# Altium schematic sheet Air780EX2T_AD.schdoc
size 124 x 121 mm
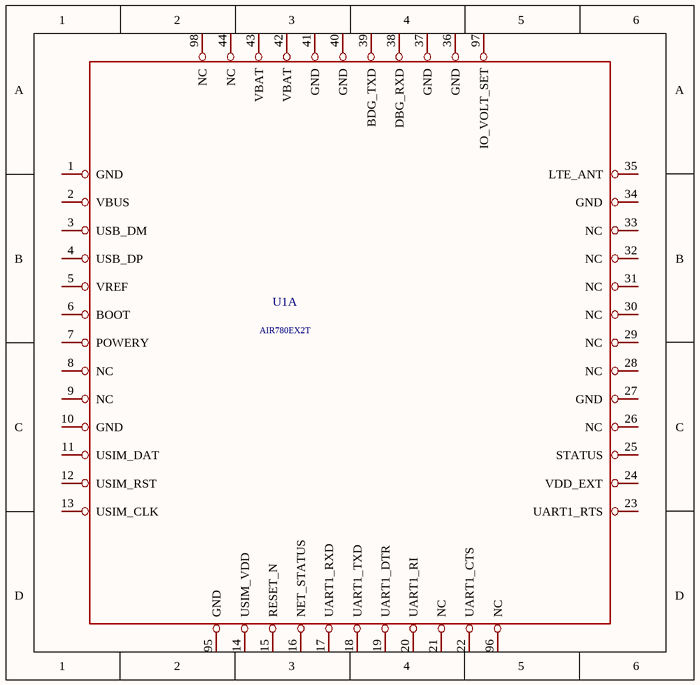
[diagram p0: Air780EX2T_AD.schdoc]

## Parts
U1  AIR780EX2T  (part A of 2)

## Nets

Not connected (* = marked no-connect by the designer): U1 1(GND) 2(VBUS) 3(USB_DM) 4(USB_DP) 5(VREF) 6(BOOT) 7(POWERY) 8(NC) 9(NC) 10(GND) 11(USIM_DAT) 12(USIM_RST) 13(USIM_CLK) 14(USIM_VDD) 15(RESET_N) 16(NET_STATUS) 17(UART1_RXD) 18(UART1_TXD) 19(UART1_DTR) 20(UART1_RI) 21(NC) 22(UART1_CTS) 23(UART1_RTS) 24(VDD_EXT) 25(STATUS) 26(NC) 27(GND) 28(NC) 29(NC) 30(NC) 31(NC) 32(NC) 33(NC) 34(GND) 35(LTE_ANT) 36(GND) 37(GND) 38(DBG_RXD) 39(BDG_TXD) 40(GND) 41(GND) 42(VBAT) 43(VBAT) 44(NC) 95(GND) 96(NC) 97(IO_VOLT_SET) 98(NC)

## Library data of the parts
U1 = AIR780EX2T: Add into BOM: yes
